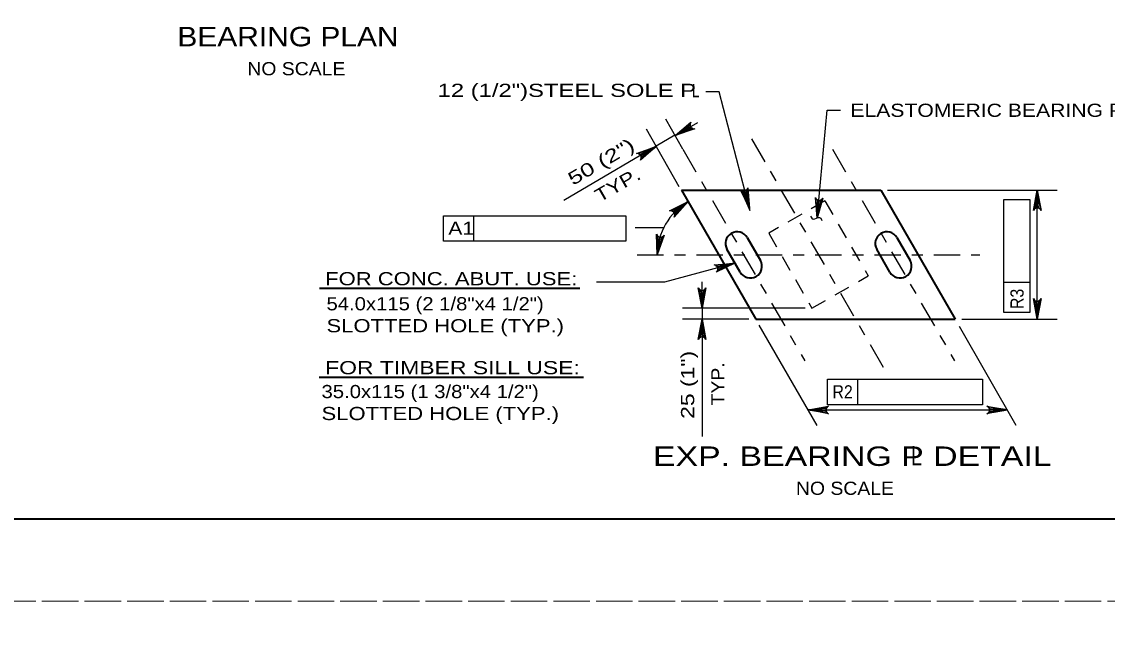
# Model space of a CAD drawing. Extents: x -11 to 79, y -154 to 0.
# Drawn here: x 4.04 to 13.92, y -132.38 to -126.72 of the extents above; entities that cross this region are included whole.
import ezdxf
from ezdxf.enums import TextEntityAlignment as Align

# ---------------------------------------------------------------- set-up
doc = ezdxf.new("R2010")
doc.units = 0
doc.header["$LTSCALE"] = 0.048
for name, pattern in [('DOT_DASHED', [7.7, 5, -1.2, 0.3, -1.2]), ('LONG_DASHED', [7.5, 6, -1.5]), ('MEDIUM_DASHED', [4.5, 3, -1.5])]:
    doc.linetypes.add(name, pattern=pattern)
for name, color, linetype, lineweight in [('1', 7, 'Continuous', 25), ('3', 7, 'Continuous', 25), ('4', 7, 'Continuous', 25), ('63', 7, 'LONG_DASHED', 13)]:
    doc.layers.add(name, color=color, linetype=linetype, lineweight=lineweight)

msp = doc.modelspace()

# ---------------------------------------------------------------- hatches: boundary and pattern name
at = {"layer": '4'}
for points in [[(10.08125, -127.6825), (10.10117, -127.71717), (9.98725, -127.75975)], [(9.70267, -127.9005), (9.72258, -127.93517), (9.81658, -127.858)], [(13.26483, -128.37542), (13.30483, -128.37542), (13.28483, -128.25542)], [(10.65775, -128.31958), (10.61908, -128.32967), (10.6685, -128.44075)], [(11.31317, -128.39217), (11.27333, -128.3885), (11.28217, -128.50983)], [(10.4015, -128.93575), (10.412, -128.97433), (10.5225, -128.9235)], [(10.21367, -129.21242), (10.25367, -129.21242), (10.23367, -129.33242)], [(13.26483, -129.31083), (13.30483, -129.31083), (13.28483, -129.43083)], [(10.21367, -129.55083), (10.25367, -129.55083), (10.23367, -129.43083)], [(11.31908, -130.23867), (11.31908, -130.27867), (11.19908, -130.25867)], [(12.89342, -130.23867), (12.89342, -130.27867), (13.01342, -130.25867)]]:
    msp.add_hatch(color=256, dxfattribs=at).paths.add_polyline_path(points)

# ---------------------------------------------------------------- linework, layer by layer
at = {"layer": '1', "lineweight": 35}
msp.add_lwpolyline([(1.75, -131.25), (33.25, -131.25), (33.25, -110.75), (1.75, -110.75)], close=True, dxfattribs=at)
at = {"layer": '3', "linetype": 'DOT_DASHED'}
for p, q in [((10.05733, -127.88158), (11.16833, -129.81075)), ((10.68475, -127.79017), (11.901, -129.90217)), ((11.42033, -127.88158), (12.53125, -129.81075))]:
    msp.add_line(p, q, dxfattribs=at)
at = {"layer": '3', "lineweight": 35}
for p, q in [((10.0455, -128.25542), (11.85983, -128.25542)), ((10.0455, -128.25542), (10.72233, -129.43083)), ((11.85983, -128.25542), (12.53667, -129.43083)), ((10.6445, -128.689), (10.76433, -128.89708)), ((12.00742, -128.689), (12.12725, -128.89708)), ((10.58008, -129.00317), (10.46025, -128.79508)), ((11.943, -129.00317), (11.82317, -128.79508)), ((10.72233, -129.43083), (12.53667, -129.43083))]:
    msp.add_line(p, q, dxfattribs=at)
at = {"layer": '3', "linetype": 'MEDIUM_DASHED'}
msp.add_line((11.3515, -128.35383), (11.74533, -129.03767), dxfattribs=at)
msp.add_lwpolyline([(11.3515, -128.35383), (10.83975, -128.6485), (11.23358, -129.33242), (11.74533, -129.03767)], dxfattribs=at)
at = {"layer": '3', "lineweight": 35}
for centre, start, end in [((10.55233, -128.74197), 29.93576, 209.93576), ((11.91526, -128.74197), 29.93576, 209.93576), ((10.67219, -128.95011), 209.93576, 29.93576), ((12.03512, -128.95011), 209.93576, 29.93576)]:
    msp.add_arc(centre, 0.1063, start, end, dxfattribs=at)
at = {"layer": '4'}
for p, q in [((11.28208, -128.51108), (11.37317, -127.52858)), ((11.37317, -127.52858), (11.49317, -127.52858)), ((10.05733, -127.88158), (9.90208, -127.60825)), ((9.98792, -127.75933), (10.19517, -127.63992)), ((9.98642, -127.75675), (8.97433, -128.35208)), ((10.025, -128.22675), (9.72683, -127.702)), ((11.92233, -128.25542), (13.46483, -128.25542)), ((13.28483, -129.43083), (13.28483, -128.25542)), ((12.98167, -129.37167), (12.98167, -128.34183)), ((12.98167, -128.34183), (13.21792, -128.34183)), ((7.87875, -128.48983), (9.53967, -128.48983)), ((7.87875, -128.7205), (7.87875, -128.48983)), ((8.15433, -128.7205), (8.15433, -128.48983)), ((9.53967, -128.48983), (9.53967, -128.7205)), ((9.88275, -128.60017), (9.6235, -128.60017)), ((9.53967, -128.7205), (7.87875, -128.7205)), ((10.23367, -129.33242), (10.23367, -129.09242)), ((13.21792, -129.09608), (12.98167, -129.09608)), ((11.17108, -129.33242), (10.05367, -129.33242)), ((10.23367, -129.33242), (10.23367, -130.5005)), ((10.65983, -129.43083), (10.05367, -129.43083)), ((12.59917, -129.43083), (13.46483, -129.43083)), ((11.27992, -130.399), (10.754, -129.48575)), ((13.09425, -130.399), (12.576, -129.49908)), ((11.3745, -129.97708), (12.7865, -129.97708)), ((11.3745, -130.21333), (11.3745, -129.97708)), ((11.65008, -130.21333), (11.65008, -129.97708)), ((12.7865, -129.97708), (12.7865, -130.21333)), ((12.7865, -130.21333), (11.3745, -130.21333)), ((11.19908, -130.25867), (13.01342, -130.25867))]:
    msp.add_line(p, q, dxfattribs=at)
at = {"layer": '4', "linetype": 'DOT_DASHED'}
msp.add_line((9.64208, -128.84617), (12.76267, -128.84617), dxfattribs=at)
at = {"layer": '4', "lineweight": 35}
for p, q in [((6.75133, -129.14817), (9.11942, -129.14817)), ((6.74683, -129.96125), (9.15308, -129.96125))]:
    msp.add_line(p, q, dxfattribs=at)
at = {"layer": '4'}
for points in [[(10.66425, -128.42425), (10.38867, -127.36125), (10.26867, -127.36125)], [(9.98792, -127.75933), (10.132, -127.636), (10.1245, -127.65175), (10.12433, -127.66633), (10.12875, -127.67817), (10.13683, -127.688), (10.1495, -127.69508), (10.16692, -127.69658), (9.98792, -127.75933), (10.1495, -127.69508), (10.13683, -127.688), (9.98792, -127.75933), (10.12875, -127.67817), (10.12433, -127.66633), (9.98792, -127.75933), (10.1245, -127.65175)], [(9.81517, -127.8575), (9.67225, -127.98217), (9.67958, -127.96625), (9.67958, -127.95175), (9.67508, -127.93992), (9.66692, -127.93017), (9.65417, -127.92317), (9.63675, -127.92192), (9.81517, -127.8575), (9.65417, -127.92317), (9.66692, -127.93017), (9.81517, -127.8575), (9.67508, -127.93992), (9.67958, -127.95175), (9.81517, -127.8575), (9.67958, -127.96625)], [(10.66425, -128.42425), (10.58367, -128.25258), (10.59683, -128.264), (10.61083, -128.268), (10.6235, -128.26692), (10.635, -128.26175), (10.64525, -128.25142), (10.65133, -128.235), (10.66425, -128.42425), (10.64525, -128.25142), (10.635, -128.26175), (10.66425, -128.42425), (10.6235, -128.26692), (10.61083, -128.268), (10.66425, -128.42425), (10.59683, -128.264)], [(13.28483, -128.25542), (13.31975, -128.44183), (13.30983, -128.4275), (13.29733, -128.42008), (13.28483, -128.41792), (13.27233, -128.42008), (13.25983, -128.4275), (13.24992, -128.44183), (13.28483, -128.25542), (13.25983, -128.4275), (13.27233, -128.42008), (13.28483, -128.25542), (13.28483, -128.41792), (13.29733, -128.42008), (13.28483, -128.25542), (13.30983, -128.4275)], [(10.10583, -128.36025), (9.979, -128.50142), (9.98442, -128.48475), (9.98267, -128.47033), (9.97683, -128.45908), (9.9675, -128.45042), (9.954, -128.445), (9.93658, -128.44592), (10.10583, -128.36025), (9.954, -128.445), (9.9675, -128.45042), (10.10583, -128.36025), (9.97683, -128.45908), (9.98267, -128.47033), (10.10583, -128.36025), (9.98442, -128.48475)], [(11.28208, -128.51108), (11.2645, -128.32225), (11.27308, -128.3375), (11.28483, -128.346), (11.29708, -128.34925), (11.30975, -128.34833), (11.32283, -128.34208), (11.33408, -128.32867), (11.28208, -128.51108), (11.32283, -128.34208), (11.30975, -128.34833), (11.28208, -128.51108), (11.29708, -128.34925), (11.28483, -128.346), (11.28208, -128.51108), (11.27308, -128.3375)], [(13.21792, -128.34183), (13.21792, -129.37167), (12.98167, -129.37167)], [(9.82583, -128.84592), (9.81958, -128.65633), (9.82733, -128.67208), (9.8385, -128.68125), (9.85058, -128.68533), (9.86325, -128.68508), (9.87675, -128.67967), (9.88867, -128.667), (9.82583, -128.84592), (9.87675, -128.67967), (9.86325, -128.68508), (9.82583, -128.84592), (9.85058, -128.68533), (9.8385, -128.68125), (9.82583, -128.84592), (9.82733, -128.67208)], [(10.53267, -128.92075), (9.89167, -129.0955), (9.272, -129.0955)], [(10.53267, -128.92075), (10.362, -129.0035), (10.37325, -128.99008), (10.37708, -128.97608), (10.37592, -128.9635), (10.3705, -128.952), (10.36008, -128.94192), (10.34358, -128.93608), (10.53267, -128.92075), (10.36008, -128.94192), (10.3705, -128.952), (10.53267, -128.92075), (10.37592, -128.9635), (10.37708, -128.97608), (10.53267, -128.92075), (10.37325, -128.99008)], [(10.23367, -129.33242), (10.19875, -129.146), (10.20867, -129.16033), (10.22117, -129.16775), (10.23367, -129.16992), (10.24617, -129.16775), (10.25867, -129.16033), (10.26858, -129.146), (10.23367, -129.33242), (10.25867, -129.16033), (10.24617, -129.16775), (10.23367, -129.33242), (10.23367, -129.16992), (10.22117, -129.16775), (10.23367, -129.33242), (10.20867, -129.16033)], [(13.28483, -129.43083), (13.24992, -129.24442), (13.25983, -129.25875), (13.27233, -129.26617), (13.28483, -129.26833), (13.29733, -129.26617), (13.30983, -129.25875), (13.31975, -129.24442), (13.28483, -129.43083), (13.30983, -129.25875), (13.29733, -129.26617), (13.28483, -129.43083), (13.28483, -129.26833), (13.27233, -129.26617), (13.28483, -129.43083), (13.25983, -129.25875)], [(10.23367, -129.43083), (10.26858, -129.61725), (10.25867, -129.60292), (10.24617, -129.5955), (10.23367, -129.59333), (10.22117, -129.5955), (10.20867, -129.60292), (10.19875, -129.61725), (10.23367, -129.43083), (10.20867, -129.60292), (10.22117, -129.5955), (10.23367, -129.43083), (10.23367, -129.59333), (10.24617, -129.5955), (10.23367, -129.43083), (10.25867, -129.60292)], [(11.19908, -130.25867), (11.3855, -130.22375), (11.37117, -130.23367), (11.36375, -130.24617), (11.36158, -130.25867), (11.36375, -130.27117), (11.37117, -130.28367), (11.3855, -130.29358), (11.19908, -130.25867), (11.37117, -130.28367), (11.36375, -130.27117), (11.19908, -130.25867), (11.36158, -130.25867), (11.36375, -130.24617), (11.19908, -130.25867), (11.37117, -130.23367)], [(13.01342, -130.25867), (12.827, -130.29358), (12.84133, -130.28367), (12.84875, -130.27117), (12.85092, -130.25867), (12.84875, -130.24617), (12.84133, -130.23367), (12.827, -130.22375), (13.01342, -130.25867), (12.84133, -130.23367), (12.84875, -130.24617), (13.01342, -130.25867), (12.85092, -130.25867), (12.84875, -130.27117), (13.01342, -130.25867), (12.84133, -130.28367)]]:
    msp.add_lwpolyline(points, dxfattribs=at)
for points in [[(10.08125, -127.6825), (10.10117, -127.71717), (9.98725, -127.75975)], [(9.70267, -127.9005), (9.72258, -127.93517), (9.81658, -127.858)], [(13.26483, -128.37542), (13.30483, -128.37542), (13.28483, -128.25542)], [(10.65775, -128.31958), (10.61908, -128.32967), (10.6685, -128.44075)], [(11.31317, -128.39217), (11.27333, -128.3885), (11.28217, -128.50983)], [(10.4015, -128.93575), (10.412, -128.97433), (10.5225, -128.9235)], [(10.21367, -129.21242), (10.25367, -129.21242), (10.23367, -129.33242)], [(13.26483, -129.31083), (13.30483, -129.31083), (13.28483, -129.43083)], [(10.21367, -129.55083), (10.25367, -129.55083), (10.23367, -129.43083)], [(11.31908, -130.23867), (11.31908, -130.27867), (11.19908, -130.25867)], [(12.89342, -130.23867), (12.89342, -130.27867), (13.01342, -130.25867)]]:
    msp.add_lwpolyline(points, close=True, dxfattribs=at)
msp.add_arc((10.38568, -128.84616), 0.5599, 119.93576, 179.99657, dxfattribs=at)
msp.add_open_spline([(11.22183, -128.49342), (11.2475, -128.56617), (11.30317, -128.45917), (11.32458, -128.53192)], degree=3, dxfattribs=at)
at = {"layer": '63'}
for points in [[(0, -132), (34, -132), (34, -110), (0, -110)], [(0, -154), (34, -154), (34, -132), (0, -132)]]:
    msp.add_lwpolyline(points, close=True, dxfattribs=at)

# ---------------------------------------------------------------- texts
at = {"layer": '4'}
for s, height, width, p in [('BEARING PLAN', 0.1772, 1.15, (6.46354, -126.94633)), ('A1', 0.12, 1.2, (8.04079, -128.66333)), ('R2', 0.12, 0.9, (11.51262, -130.15333)), ('EXP. BEARING P DETAIL', 0.1772, 1.3, (11.60096, -130.76825)), ('L', 0.1772, 0.75, (12.18525, -130.76325))]:
    msp.add_text(s, height=height, dxfattribs=dict(at, width=width)).set_placement(p, align=Align.CENTER)
for s, width, p in [('NO SCALE', 1.1, (6.0935, -127.21008)), ('12 (1/2")STEEL SOLE P', 1.35, (7.82583, -127.40708)), ('L', 0.75, (10.14183, -127.40958)), ('ELASTOMERIC BEARING PAD', 1.2, (11.58317, -127.58867)), ('FOR CONC. ABUT. USE:', 1.25, (6.802, -129.123)), ('54.0x115 (2 1/8"x4 1/2")', 1.15, (6.81417, -129.35117)), ('SLOTTED HOLE (TYP.)', 1.25, (6.81417, -129.55117)), ('FOR TIMBER SILL USE:', 1.3, (6.80192, -129.93333)), ('35.0x115 (1 3/8"x4 1/2")', 1.15, (6.76892, -130.15092)), ('SLOTTED HOLE (TYP.)', 1.25, (6.76892, -130.35092)), ('NO SCALE', 1.1, (11.08775, -131.03192))]:
    msp.add_text(s, height=0.12, dxfattribs=dict(at, width=width)).set_placement(p)
for s, rotation, width, p in [('50 (2")', 30.466, 1.4, (9.34408, -128.04889)), ('TYP.', 29.936, 1.25, (9.49402, -128.25941)), ('R3', 90, 0.9, (13.16075, -129.24696)), ('25 (1")', 90, 1.3, (10.16142, -130.03004)), ('TYP.', 90, 1.1, (10.4365, -130.02096))]:
    msp.add_text(s, height=0.12, rotation=rotation, dxfattribs=dict(at, width=width)).set_placement(p, align=Align.CENTER)

doc.saveas('drawing.dxf')
